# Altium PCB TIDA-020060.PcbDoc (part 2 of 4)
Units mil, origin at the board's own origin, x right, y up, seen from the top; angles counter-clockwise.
Board outline 2114.94 x 3612.21 mil, 4 copper layers (Top Layer, Signal Layer 1, Signal Layer 2, Bottom Layer), stack 61.811 mil thick; 272 components, 167 nets, 840 pads, 352 vias.
Unrouted connection lines stored in the file: 261.
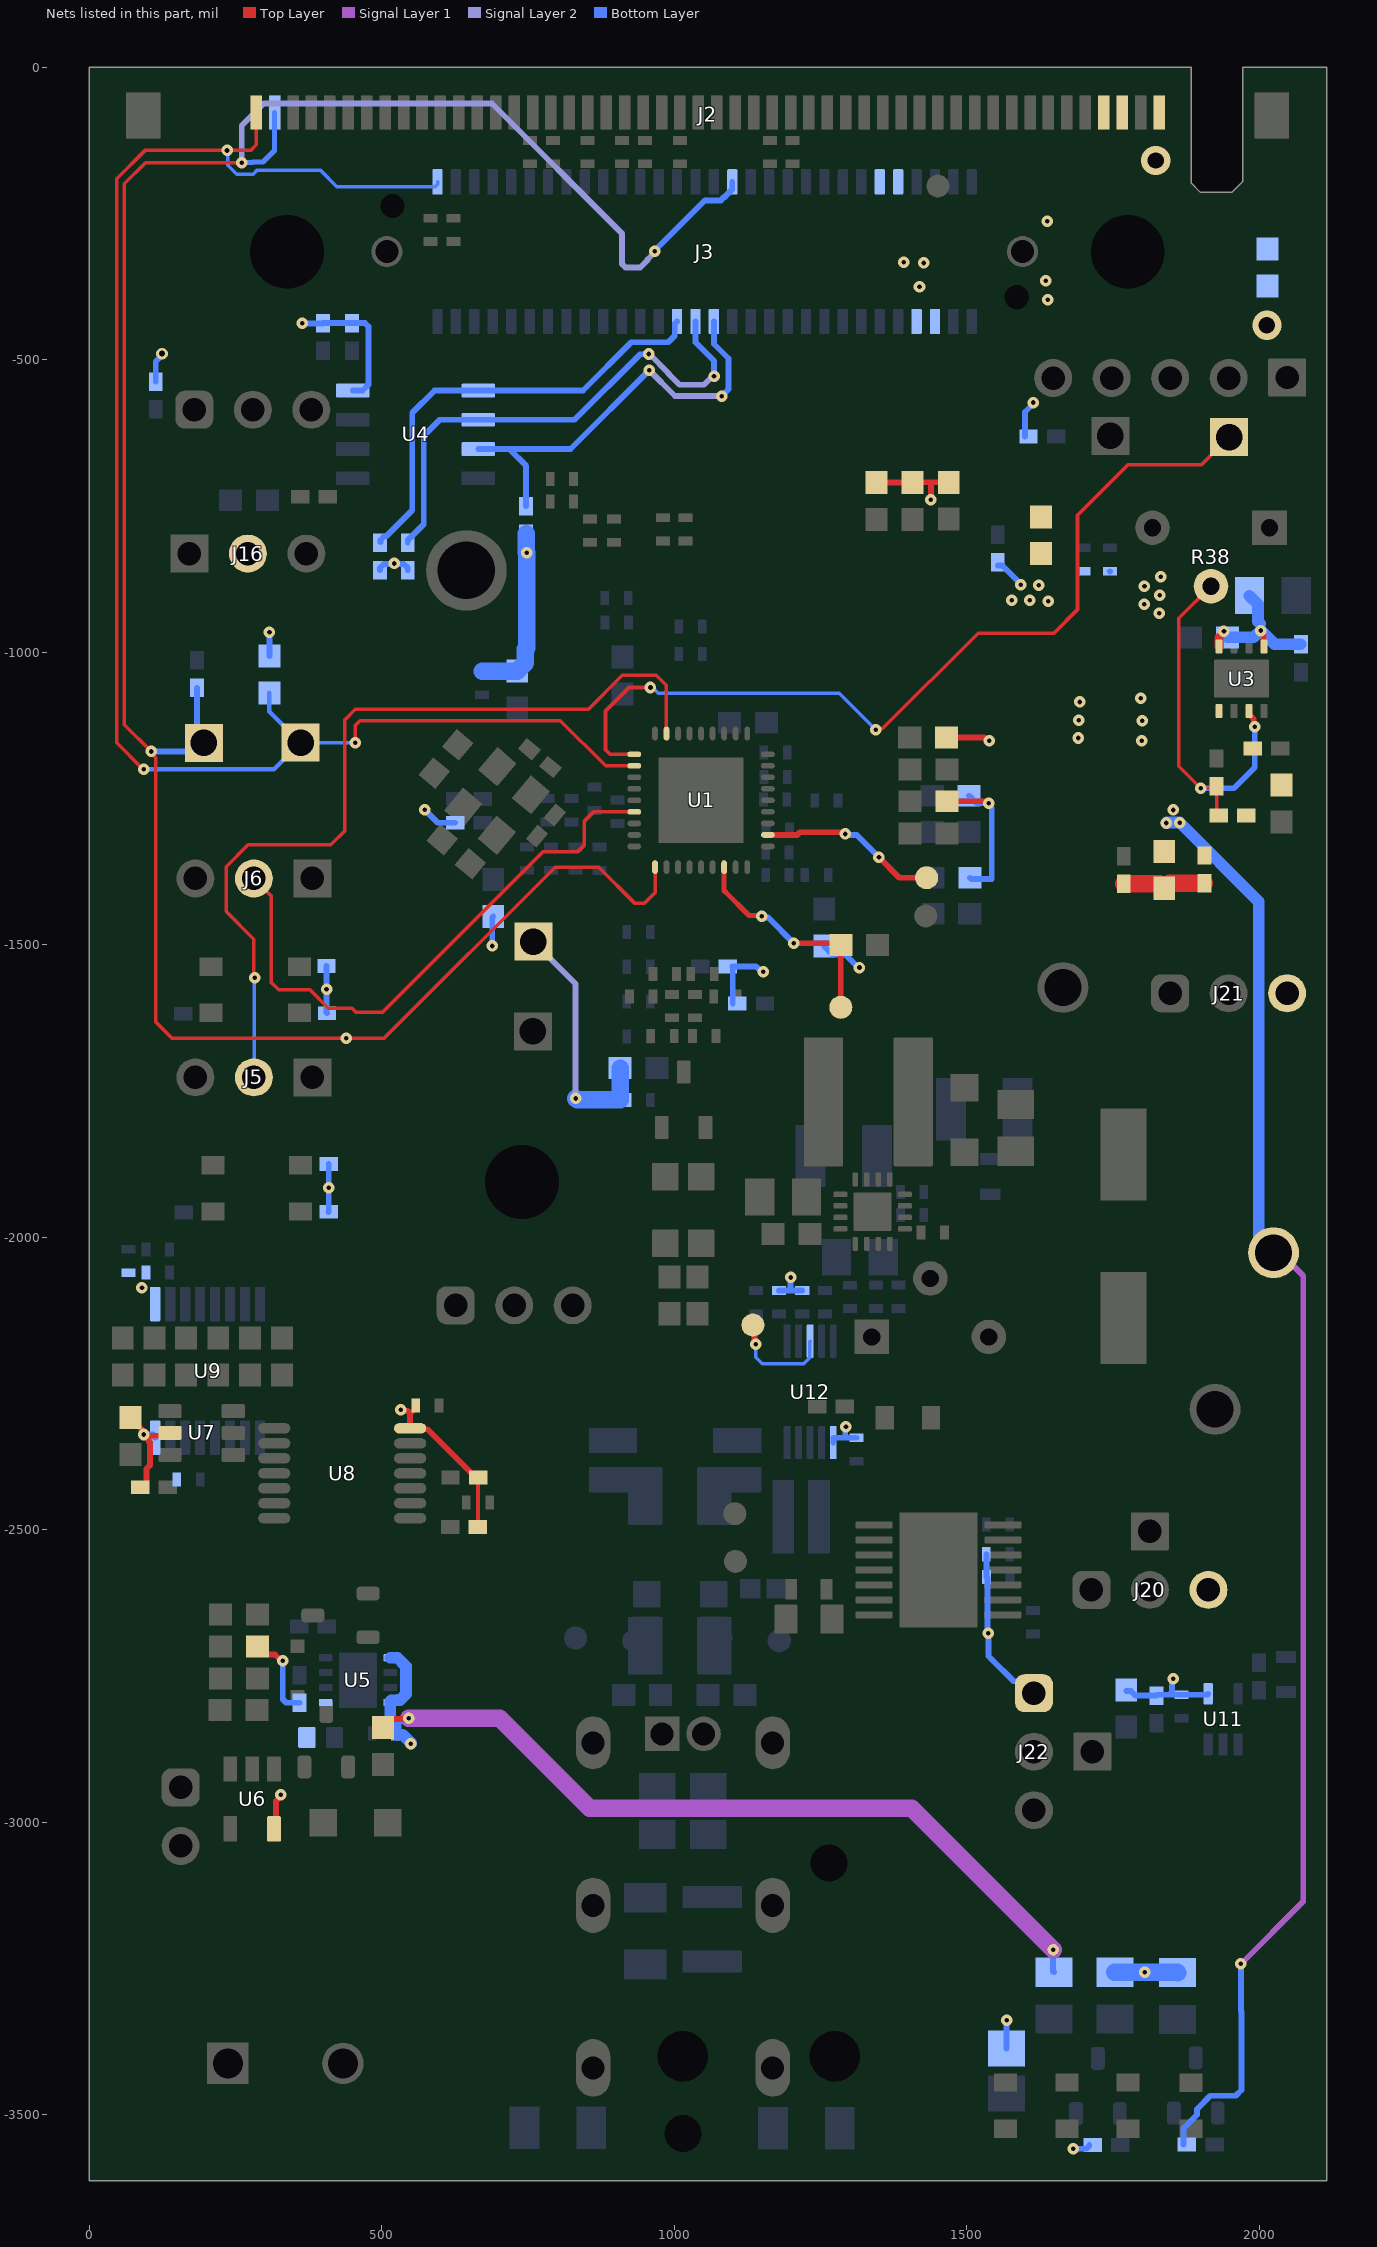
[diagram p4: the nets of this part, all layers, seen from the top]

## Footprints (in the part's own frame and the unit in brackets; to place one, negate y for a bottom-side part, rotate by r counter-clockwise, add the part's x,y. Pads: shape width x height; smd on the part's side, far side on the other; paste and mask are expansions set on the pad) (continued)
Samtec_ERF8-050-01-x-D-EM2 [mm] "Receptacle, 0.8mm, 50x2, Edge Mount"
  rect 0.5x1.48 smd paste-1: 1(-19.6,-2.06) 3(-18.8,-2.06) 5(-18,-2.06) 7(-17.2,-2.06) 9(-16.4,-2.06) 11(-15.6,-2.06) 13(-14.8,-2.06) 15(-14,-2.06) 17(-13.2,-2.06) 19(-12.4,-2.06) 21(-11.6,-2.06) 23(-10.8,-2.06) 25(-10,-2.06) 27(-9.2,-2.06) 29(-8.4,-2.06) 31(-7.6,-2.06) 33(-6.8,-2.06) 35(-6,-2.06) 37(-5.2,-2.06) 39(-4.4,-2.06) 41(-3.6,-2.06) 43(-2.8,-2.06) 45(-2,-2.06) 47(-1.2,-2.06) 49(-0.4,-2.06) 51(0.4,-2.06) 53(1.2,-2.06) 55(2,-2.06) 57(2.8,-2.06) 59(3.6,-2.06) 61(4.4,-2.06) 63(5.2,-2.06) 65(6,-2.06) 67(6.8,-2.06) 69(7.6,-2.06) 71(8.4,-2.06) 73(9.2,-2.06) 75(10,-2.06) 77(10.8,-2.06) 79(11.6,-2.06) 81(12.4,-2.06) 83(13.2,-2.06) 85(14,-2.06) 87(14.8,-2.06) 89(15.6,-2.06) 91(16.4,-2.06) 93(17.2,-2.06) 95(18,-2.06) 97(18.8,-2.06) 99(19.6,-2.06)
  rect 0.5x1.48 smd far side paste-1: 2(-19.6,-2.06) 4(-18.8,-2.06) 6(-18,-2.06) 8(-17.2,-2.06) 10(-16.4,-2.06) 12(-15.6,-2.06) 14(-14.8,-2.06) 16(-14,-2.06) 18(-13.2,-2.06) 20(-12.4,-2.06) 22(-11.6,-2.06) 24(-10.8,-2.06) 26(-10,-2.06) 28(-9.2,-2.06) 30(-8.4,-2.06) 32(-7.6,-2.06) 34(-6.8,-2.06) 36(-6,-2.06) 38(-5.2,-2.06) 40(-4.4,-2.06) 42(-3.6,-2.06) 44(-2.8,-2.06) 46(-2,-2.06) 48(-1.2,-2.06) 50(-0.4,-2.06) 52(0.4,-2.06) 54(1.2,-2.06) 56(2,-2.06) 58(2.8,-2.06) 60(3.6,-2.06) 62(4.4,-2.06) 64(5.2,-2.06) 66(6,-2.06) 68(6.8,-2.06) 70(7.6,-2.06) 72(8.4,-2.06) 74(9.2,-2.06) 76(10,-2.06) 78(10.8,-2.06) 80(11.6,-2.06) 82(12.4,-2.06) 84(13.2,-2.06) 86(14,-2.06) 88(14.8,-2.06) 90(15.6,-2.06) 92(16.4,-2.06) 94(17.2,-2.06) 96(18,-2.06) 98(18.8,-2.06) 100(19.6,-2.06)
  rect 1.5x2 smd: MP1(-24.5,-2.2) MP3(24.5,-2.2)
  rect 1.5x2 smd far side: MP2(-24.5,-2.2) MP4(24.5,-2.2)
  silkscreen extent -26.5,-5.2 26,-0.17, body extent -26,-5.2 26,7, height 2.14
SM_RADIAL_F [mm] "8 x 10.2mm:  Panasonic F"
  rect 4x2 smd: 1(-3.55,0) 2(3.55,0)
  silkscreen extent -4.25,-4.25 4.25,4.25, body extent -4.25,-4.25 4.25,4.25, height 10.5
SOD-123W [mm] "NXP recommended land pattern"
  rect 1.2x1.2 smd paste-0.05: 1(-1.4,0) 2(1.4,0)
  silkscreen extent -2.64,-1.14 1.68,1.14, body extent -1.85,-0.95 1.85,0.95, height 1.1
SOD-323 [mm] "NXP recommended land pattern"
  rect 0.6x0.6 smd paste-0.05: 1(-1.1,0) 2(1.1,0)
  silkscreen extent -2.06,-0.86 1.53,0.86, body extent -1.3,-0.67 1.3,0.68, height 1.1
SOIC-8 [mm] "duplicate of SO-8.  SOIC, 8-Leads, Body 5.0x4.0mm (max), Pitch 1.27mm, IPC Medium Density"
  rrect17% 1.45x0.6 smd: 1(-2.725,1.905) 2(-2.725,0.635) 3(-2.725,-0.635) 4(-2.725,-1.905) 5(2.725,-1.905) 6(2.725,-0.635) 7(2.725,0.635) 8(2.725,1.905)
  silkscreen extent -3.5,-2.5 0.9,2.5, body extent -3,-2.45 3,2.45, height 1.63
SOT-23 [mm] "SOT23, 3-Leads, Body 2.9x1.3mm, Pitch 0.95mm, Lead Span 2.5mm, IPC Medium Density"
  rrect50% 1x0.6 smd: 1(-1.2,0.95) 2(-1.2,-0.95) 3(1.2,0)
  silkscreen extent -1.62,-1.5 0.7,1.5, body extent -1.16,-1.45 1.21,1.45, height 1
SPC02SYAN [mil] "SULLINS"
  round 1 on Mech3: 0(0,0)
  body extent -98,-47 99,47, height 366
TE_1PORT_B1-B [mm] "Header, 1.8mm, 2x1, TH"
  rect 1.5x1.5 hole 1: 1(-0.9,17.35)
  round 1.5 hole 1: 2(0.9,17.35)
  round 0 hole 2.2 unplated: MH1(0,3.35) MH2(6.6,3.35)
  round 0 hole 1.6 unplated: MH3(6.35,11.75) MH4(0,0)
  oval 1.5x2.3 hole 1 slot 1.775 at 90 deg: S1(-3.9,16.963) S4(3.9,16.963)
  oval 1.5x2.4 hole 1 slot 1.89 at 90 deg: S2(-3.9,9.905) S5(3.9,9.905)
  oval 1.5x2.5 hole 1 slot 2 at 90 deg: S3(-3.9,2.85) S6(3.9,2.85)
  silkscreen extent -7.45,-1.8 10.3,20, body extent -7.45,-1.8 10.3,19.3, height 13.5
TI_Stacked_Overlay_Small [mil]
  silkscreen extent -418,-98 418,98
TP_SM_1MM [mm] "1mm Test Point, SMT"
  round 1 smd paste-0.5: 1(0,0)
TRIM_3266W [mm] "Bourns 3266W series REV 08/10"
  rect 1.5x1.5 hole 0.75: 1(0,0)
  round 1.5 hole 0.75: 2(2.54,-2.54) 3(0,-5.08)
  silkscreen extent -1.2,-6.09 3.68,1.01, body extent -1.2,-6.09 3.68,1.01, height 8.45
TSW-101-07-G-S [mm] "Samtec 100mil, 1pos, 230 mil above insulator"
  rrect6% 1.65x1.65 hole 1.016: 1(0,0)
  silkscreen extent -1.27,-1.27 1.27,1.27, body extent -1.27,-1.27 1.27,1.27, height 8.38
TSW-102-07-G-S [mm] "Samtec 100mil, 1x2, 230 mil above insulator"
  rrect50% 1.65x1.65 hole 1.016: 1(-1.27,0)
  round 1.65 hole 1.016: 2(1.27,0)
  silkscreen extent -3.3,-1.27 2.54,1.44, body extent -2.54,-1.27 2.54,1.27, height 8.38
TSW-103-07-G-S [mm] "Samtec 100mil, 1x3, 230 mil above insulator"
  rrect50% 1.65x1.65 hole 1.016: 1(-2.54,0)
  round 1.65 hole 1.016: 2(0,0) 3(2.54,0)
  body extent -3.81,-1.27 3.81,1.27, height 8.38
TSW-103-07-X-S [mm] "Samtec Header, 100mil, 1x3"
  rect 1.65x1.65 hole 1.016: 1(-2.54,0)
  round 1.65 hole 1.016: 2(0,0) 3(2.54,0)
  silkscreen extent -4.57,-1.52 4.06,1.52, body extent -3.81,-1.27 3.81,1.27, height 8.38
TSW-105-07-X-S [mm] "Samtec 100mil, 1x5, 230 mil above insulator"
  rrect6% 1.65x1.65 hole 1.016: 1(-5.08,-0.025)
  round 1.65 hole 1.016: 2(-2.54,0) 3(0,0) 4(2.54,0) 5(5.08,0)
  silkscreen extent -6.38,-1.25 6.37,1.25, body extent -6.35,-1.27 6.35,1.27, height 8.38
WEEE_Minimum [mil] "WEEElie bin"
  silkscreen extent -95,-172 99,104
WURTH_61300111121 [mm] "Header, 2.54 mm, 1x1, TH"
  rect 1.65x1.65 hole 1.15: 1(0,0)
  silkscreen extent -1.27,-1.27 1.27,1.27, body extent -1.27,-1.27 1.27,1.27, height 8.54

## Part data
C1 C33 C34 C36 C64: library part CMP-0006279-2, "CAP, CERM, 0.1 uF, 50 V, +/- 10%, X5R, 0402", Cap_Case=0402, Manufacturer=TDK, Supplier Part Number 1=445-5942-1-ND, TempCo=X5R, Tolerance_%=10%, Value1="0.039064 ohm", Value2=50V, ValueDisplayed=0.1uF
C2 C8 C11 C15 C22 C23 C35 C41: library part CMP-0006564-3, "CAP, CERM, 10 uF, 10 V, +/- 20%, X5R, 0402", Cap_Case=0402, Manufacturer=MuRata, TempCo=X5R, Tolerance_%=20%, Value1=Unknown, Value2=10V, ValueDisplayed=10uF
C3 C6 C12 C16 C24 C38 C44: library part CMP-0085818-1, "CAP, CERM, 1 µF, 10 V,+/- 10%, X7S, AEC-Q200 Grade 1, 0402", Cap_Case=0402, Manufacturer=MuRata, TempCo=X7S, Tolerance_%=10%, Value2=10V, ValueDisplayed=1µF
C4: library part CMP-0006669-2, "CAP, CERM, 0.047 uF, 25 V, +/- 10%, X7R, 0402", Cap_Case=0402, Manufacturer=MuRata, Supplier Part Number 1=490-3254-1-ND, TempCo=X7R, Tolerance_%=10%, Value1=Unknown, Value2=25V, ValueDisplayed=0.047uF
C5 C55: library part CMP-0006279-2, "CAP, CERM, 0.1 uF, 50 V, +/- 10%, X5R, 0402", Cap_Case=0402, Manufacturer=TDK, Supplier Part Number 1=445-5942-1-ND, TempCo=X5R, Tolerance_%=10%, Value1="0.039064 ohm", Value2=50V, ValueDisplayed=100nF
C7: library part CMP-0006467-2, "CAP, CERM, 47 pF, 50 V, +/- 1%, C0G/NP0, 0402", Cap_Case=0402, Manufacturer=MuRata, Supplier Part Number 1=490-6241-1-ND, TempCo=C0G/NP0, Tolerance_%=1%, Value1=Unknown, Value2=50V, ValueDisplayed=47pF
C9: library part CMP-0006438-2, "CAP, CERM, 22 pF, 50 V, +/- 1%, C0G/NP0, 0402", Cap_Case=0402, Manufacturer=MuRata, Supplier Part Number 1=490-8589-1-ND, TempCo=C0G/NP0, Tolerance_%=1%, Value1=Unknown, Value2=50V, ValueDisplayed=22pF
C10 C20: library part CMP-0007099-4, "CAP, CERM, 0.1 uF, 100 V, +/- 10%, X7S, AEC-Q200 Grade 1, 0603", Cap_Case=0603, Manufacturer=TDK, Supplier Part Number 1=445-6938-1-ND, TempCo=X7S, Tolerance_%=10%, Value1="0.04959 ohm", Value2=100V, ValueDisplayed=0.1uF
C13 C17 C25 C37 C39 C45 C51 C63 C65: library part CMP-0006237-2, "CAP, CERM, 0.1 uF, 16 V, +/- 10%, X7R, AEC-Q200 Grade 1, 0402", Cap_Case=0402, Manufacturer=Kemet, Supplier Part Number 1=399-6828-1-ND, TempCo=X7R, Tolerance_%=10%, Value1=Unknown, Value2=16V, ValueDisplayed=0.1uF
C14 C18 C26 C40 C43 C46: library part CMP-0006658-2, "CAP, CERM, 0.01 uF, 25 V, +/- 10%, X7R, 0402", Cap_Case=0402, Manufacturer=MuRata, Supplier Part Number 1=490-1312-1-ND, TempCo=X7R, Tolerance_%=10%, Value1=Unknown, Value2=25V, ValueDisplayed=0.01uF
C19: library part CMP-0008916-2, "CAP, CERM, 1000 pF, 1000 V, +/- 10%, X7R, 1206", Cap_Case=1206, Manufacturer=MuRata, Supplier Part Number 1=490-3494-1-ND, TempCo=X7R, Tolerance_%=10%, Value1=Unknown, Value2=1000V, ValueDisplayed=1000pF
C21: library part CMP-0006438-1, "CAP, CERM, 22 pF, 50 V, +/- 1%, C0G/NP0, 0402", Cap_Case=0402, Manufacturer=MuRata, Supplier Part Number 1=490-8589-1-ND, TempCo=C0G/NP0, Tolerance_%=1%, Value1=Unknown, Value2=50V, ValueDisplayed=22pF
C27: library part CMP-0006467-1, "CAP, CERM, 47 pF, 50 V, +/- 1%, C0G/NP0, 0402", Cap_Case=0402, Manufacturer=MuRata, Supplier Part Number 1=490-6241-1-ND, TempCo=C0G/NP0, Tolerance_%=1%, Value1=Unknown, Value2=50V, ValueDisplayed=47pF
C28 C29: library part CMP-0007071-4, "CAP, CERM, 22 pF, 50 V, +/- 5%, C0G/NP0, AEC-Q200 Grade 1, 0603", Cap_Case=0603, Manufacturer=TDK, Supplier Part Number 1=445-5632-1-ND, TempCo=C0G/NP0, Tolerance_%=5%, Value1=Unknown, Value2=50V, ValueDisplayed=22pF
C30: library part CMP-0120005-1, "Multilayer Ceramic Capacitor, 4700 pF, 2000 V, ± 10%, X7R, 1210 [3225 Metric]", Digikey Part Number=399-C1210C472KGRAC7800CT-ND, Manufacturer=KEMET, Mouser Part Number=80-C1210C472KGR, Operating Temperature Range="-55°C to +125°C", TempCo=15%, Temperature Characteristic=X7R, Tolerance_%=10%, ValueDisplayed=4700pF
C31: library part CMP-0008262-2, "CAP, CERM, 10 uF, 25 V, +/- 10%, X7S, 0805", Cap_Case=0805, Manufacturer=MuRata, Supplier Part Number 1=490-10496-1-ND, TempCo=X7S, Tolerance_%=10%, Value1=Unknown, Value2=25V, ValueDisplayed=10uF
C32: library part CMP-0007058-4, "CAP, CERM, 4.7 uF, 10 V, +/- 10%, X7S, 0603", Cap_Case=0603, Manufacturer=TDK, Supplier Part Number 1=445-14258-1-ND, TempCo=X7S, Tolerance_%=10%, Value1=Unknown, Value2=10V, ValueDisplayed=4.7uF
C42: library part CMP-0084773-1, "CAP, CERM, 0.01 µF, 100 V,+/- 10%, X7R, AEC-Q200 Grade 1, 0603", Cap_Case=0603, Manufacturer=MuRata, TempCo=X7R, Tolerance_%=10%, Value2=100V, ValueDisplayed=0.01µF
C47: library part CMP-0084301-1, "CAP, CERM, 10 µF, 6.3 V,+/- 20%, X7R, 0603", Cap_Case=0603, Manufacturer="Samsung Electro-Mechanics", TempCo=X7R, Tolerance_%=20%, Value2=6.3V, ValueDisplayed=10µF
C48: library part CMP-0120003-1, "2.2 µF ±20% 10V Ceramic Capacitor X5R 0603 (1608 Metric)", Digikey Part Number=399-C0603C225M8PAC7867CT-ND, Manufacturer=KEMET, Mouser Part Number=80-C0603C225M8P, Operating Temperature Range="-55°C to +85°C", TempCo=15%, Temperature Characteristic=X5R, Tolerance_%=20%, ValueDisplayed=2.2uF
C49: library part CMP-0084375-1, "CAP, CERM, 1 µF, 16 V,+/- 20%, X5R, 0402", Cap_Case=0402, Manufacturer=MuRata, TempCo=X5R, Tolerance_%=20%, Value2=16V, ValueDisplayed=1µF
C50: library part CMP-0006828-4, "CAP, CERM, 0.01 uF, 16 V, +/- 10%, X7R, 0603", Cap_Case=0603, Manufacturer="Wurth Elektronik", Supplier Part Number 1=732-7959-1-ND, TempCo=X7R, Tolerance_%=10%, Value1=Unknown, Value2=16V, ValueDisplayed=0.01uF
C52: library part CMP-0007080-5, "CAP, CERM, 0.068 uF, 50 V, +/- 10%, X7R, AEC-Q200 Grade 1, 0603", Cap_Case=0603, Manufacturer=TDK, Supplier Part Number 1=445-5665-1-ND, TempCo=X7R, Tolerance_%=10%, Value1="0.035979 ohm", Value2=50V, ValueDisplayed=0.068uF
C53: library part CMP-0007411-4, "CAP, CERM, 0.15 uF, 25 V, +/- 10%, X7R, 0603", Cap_Case=0603, Manufacturer=MuRata, Supplier Part Number 1=490-3289-1-ND, TempCo=X7R, Tolerance_%=10%, Value1=Unknown, Value2=25V, ValueDisplayed=0.15uF
C54: library part CMP-0006832-5, "CAP, CERM, 0.1 uF, 25 V, +/- 10%, X7R, 0603", Cap_Case=0603, Manufacturer="Wurth Elektronik", Supplier Part Number 1=710-885012206071, TempCo=X7R, Tolerance_%=10%, Value1=Unknown, Value2=25V, ValueDisplayed=0.1uF
C56: library part CMP-0007886-2, "CAP, CERM, 0.1 uF, 100 V, +/- 10%, X7R, 0805", Cap_Case=0805, Manufacturer=TDK, Supplier Part Number 1=445-1418-1-ND, TempCo=X7R, Tolerance_%=10%, Value1="0.020726 ohm", Value2=100V, ValueDisplayed=0.1uF
C57 C70: library part CMP-0009182-2, "CAP, CERM, 4.7 uF, 100 V, +/- 10%, X7S, 1210", Cap_Case=1210, Manufacturer=MuRata, Supplier Part Number 1=81-GRM32DC72A475KE1L, TempCo=X7S, Tolerance_%=10%, Value1=Unknown, Value2=100V, ValueDisplayed=4.7uF
C58 C68: library part CMP-0007469-4, "CAP, CERM, 0.1 uF, 100 V, +/- 10%, X7R, 0603", Cap_Case=0603, Manufacturer=MuRata, Supplier Part Number 1=490-3285-1-ND, TempCo=X7R, Tolerance_%=10%, Value1=Unknown, Value2=100V, ValueDisplayed=0.1uF
C59: library part CMP-0007980-2, "CAP, CERM, 1 uF, 100 V, +/- 10%, X7S, AEC-Q200 Grade 1, 0805", Cap_Case=0805, Manufacturer=TDK, Supplier Part Number 1=445-6974-1-ND, TempCo=X7S, Tolerance_%=10%, Value1="0.008255 ohm", Value2=100V, ValueDisplayed=1uF
C60: library part CMP-0006655-2, "CAP, CERM, 0.068 uF, 16 V, +/- 10%, X7R, 0402", Cap_Case=0402, Manufacturer=MuRata, Supplier Part Number 1=490-3259-1-ND, TempCo=X7R, Tolerance_%=10%, Value1=Unknown, Value2=16V, ValueDisplayed=0.068uF
C61: library part CMP-0007704-2, "CAP, CERM, 10 pF, 50 V, +/- 5%, C0G/NP0, 0805", Cap_Case=0805, Manufacturer=Kemet, Supplier Part Number 1=399-1108-1-ND, TempCo=C0G/NP0, Tolerance_%=5%, Value1="0.285 ohm", Value2=50V, ValueDisplayed=10pF
C62: library part CMP-0860997-1, "CAP, CERM, 1000 pF, 50 V,+/- 10%, X8R, AEC-Q200 Grade 0, 0402", Cap_Case=0402, Manufacturer=TDK, TempCo=X8R, Tolerance_%=10%, Value2=50V, ValueDisplayed=1000pF
C67: library part CMP-0008249-2, "CAP, CERM, 0.22 uF, 100 V, +/- 10%, X7R, 0805", Cap_Case=0805, Manufacturer=MuRata, Supplier Part Number 1=GRM21AR72A224KAC5-ND, TempCo=X7R, Tolerance_%=10%, Value1=Unknown, Value2=100V, ValueDisplayed=0.22uF
C69: library part CMP-0011202-2, "CAP, AL, 22 uF, 100 V, +/- 20%, 1.3 ohm, AEC-Q200 Grade 2, SMD", Cap_Case=F, Manufacturer=Panasonic, Supplier Part Number 1=PCE3845CT-ND, Tolerance_%=20%, Value1="1.3 ohm", Value2=100V, ValueDisplayed=22uF
D1 D5 D6 D7 D8 D9 D10 D13 D15: library part CMP-0002971-3, "LED, Green, SMD", Color=Green, Manufacturer=OSRAM, Value1=W, Value2=1.8V
D2 D3: library part CMP-0086344-2, "Diode, TVS, Bi, AEC-Q101, 0603", Manufacturer=Panasonic
D4: library part CMP-0085742-1, "Diode, Zener, 5.6 V, 300 mW, AEC-Q101, SOD-323", Manufacturer="ON Semiconductor", Power_W=300mW, Value1=0.3W
D11 D12: library part CMP-0076989-2, "Diode, Schottky, 60 V, 2 A, SOD-123W", Manufacturer=Nexperia, Value1=2A, Value2=0.53V
FB1: library part CMP-06046-000009-2, "Chip Ferrite Bead, 0603, 1000Ω @ 100MHz, 0.2Ω, 25%, 1A", Case Code (Imperial)=0603, Case Code (Metric)=1608, DC Resistance (DCR)=200mR, Max Current Rating=1A, Max Operating Temperature=125°C, Min Operating Temperature=-55°C, Ratings=AEC-Q200
H1 H2 H13: library part CMP-0003617-1, "Machine Screw, Round, #4-40 x 1/4, Nylon, Philips panhead", Manufacturer="B&F Fastener Supply", Supplier Part Number 1=H542-ND
J1: library part CMP-0054903-2, "Header(shrouded), 2x1, R/A, TH", Manufacturer="TE Connectivity"
J2: library part CMP-0055719-1, "Receptacle, 0.8mm, 50x2, Gold, Edge Mount", Color=Black, Current_A=2.2A, Manufacturer=Samtec, Voltage_V=200V
J3: library part CMP-0086037-1, "Receptacle, 0.8mm, 30x2, Gold, SMT", Color=Black, Current_A=800mA, Manufacturer=Molex, Voltage_V=5V
J4 J8 J9 J12 J13 J19: library part CMP-0054792-1, "Header, 2.54 mm, 1x1, Gold, TH", Manufacturer="Wurth Elektronik", Supplier Part Number 1=732-5314-ND
J5 J6 J16: library part CMP-0075407-1, "Header, 100mil, 3x1, Gold, TH", Color=Black, Current_A=6.3A, Manufacturer=Samtec, Supplier Part Number 1=SAM1029-03-ND, Voltage_V=550V
J7: library part CMP-0075411-1, "Header, 100mil, 5x1, Gold, TH", Color=Black, Current_A=6.3A, Manufacturer=Samtec, Supplier Part Number 1=SAM1029-05-ND, Voltage_V=550V
J11 J17 J20 J21 J22: library part CMP-0075407-2, "Header, 100mil, 3x1, Gold, TH", Color=Black, Current_A=6.3A, Manufacturer=Samtec, Supplier Part Number 1=SAM1029-03-ND, Voltage_V=550V
J14: library part CMP-0055502-1, "Therminal Block, 5 mm, 2-pole, TH", Manufacturer="Phoenix Contact", Supplier Part Number 1=277-1667-ND
J15: library part CMP-0075405-3, "Header, 100mil, 2x1, Gold, TH", Color=Black, Current_A=6.3A, Manufacturer=Samtec, Supplier Part Number 1=SAM1029-02-ND, Voltage_V=550V
J18 J23: library part CMP-0075403-1, "Header, 100mil, 1pos, Gold, TH", Color=Black, Current_A=6.3A, Manufacturer=Samtec, Supplier Part Number 1=SAM1029-01-ND, Voltage_V=550V
L1: library part CMP-0003343-2, "Ferrite Bead, 1000 ohm @ 100 MHz, 0.4 A, 0603", Manufacturer=MuRata, Supplier Part Number 1=490-1015-1-ND, Value1="0.5 ohm", Value2=0.4A, ValueDisplayed="1000 ohm"
L2: library part CMP-0098175-1, "Differential Mode Choke 3.9uH 540mA 0.36Ohm 3.2x2.5x2.5mm SMT", Manufacturer=TDK, Operating Temperature Range="-40°C to +150°C", Test Frequency=100kHz, Tolerance_%=20%
L3 L4: library part CMP-0003343-1, "Ferrite Bead, 1000 ohm @ 100 MHz, 0.4 A, 0603", Manufacturer=MuRata, Supplier Part Number 1=490-1015-1-ND, Value1="0.5 ohm", Value2=0.4A, ValueDisplayed="1000 ohm"
L5: library part CMP-0098176-1, "Differential Mode Choke 2.6uH 1.5A 84mOhm 7.0x6.0x3.5mm SMT", Manufacturer=TDK, Operating Temperature Range="-40°C to +150°C", Self Resonant Frequency=20MHz, Test Frequency=100kHz, Tolerance_%=20%
L6 L7: library part CMP-0121122-1, "Wire Wound Ferrite Inductor for Automotive 3.3μH ±5% 0.24Ω 425mA 1210", Manufacturer=Murata, Operating Temperature Range="-40°C to +125°C", Self Resonant Frequency=65MHz, Test Frequency=1MHz, Tolerance_%=0.05%
L8: library part CMP-0098174-1, "Common Mode Choke for Ethernet 1000BASE-T1", Manufacturer=TDK, Operating Temperature Range="to +125°C", Test Frequency=100kHz, Tolerance_%=30%
L9: library part CMP-0098310-1, "10 µH Shielded Inductor 3.3 A 70.2mOhm Max Nonstandard", Digikey Part Number=732-78438367100CT-ND, Manufacturer="Wurth Electronics", Mouser Part Number=710-78438367100, Operating Temperature Range="-40°C to +125°C", Self Resonant Frequency=13MHz, Test Frequency=100kHz, Tolerance_%=20%
L12: library part CMP-0001515-1, "Differential Mode Choke 18uH 1.8A 0.103 Ohm 7.5x7.5x7.5mm SMT", Manufacturer=TDK, Operating Temperature Range="-40°C to +150°C", Test Frequency=100kHz, Tolerance_%=20%
LBL4: library part CMP-0003625-1, "Thermal Transfer Printable Labels, 0.650\" W x 0.200\" H - 10,000 per roll", Manufacturer=Brady, Supplier Part Number 1=97C5133
Logo8: library part CMP-0074769-3, Manufacturer="Texas Instruments"
Logo9: library part CMP-0074844-1
Logo10: library part CMP-0074838-1, "Texas Instrument Corporate Signature"
Logo11: library part CMP-0074847-1, "FCC_disclaimer"
Q1 Q3: library part CMP-0000376-2, "Transistor, NPN, 45 V, 0.1 A, SOT-23", Manufacturer="ON Semiconductor", Supplier Part Number 1=BC847CLT1GOSCT-ND, Value1="0.1 A", Value2=800
Q2: library part CMP-0000325-2, "Transistor, PNP, 40 V, 0.2 A, SOT-23", Manufacturer="Fairchild Semiconductor", Supplier Part Number 1=MMBT3906FSCT-ND, Value1="0.2 A", Value2=300
Q5: library part CMP-0000971-2, "MOSFET, N-CH, 100 V, 1.4 A, SOT-23", Alternate Manufacturer=None, Manufacturer="Diodes Inc.", Supplier Part Number 1=DMN10H220L-7DICT-ND, Value1=0.2, Value2="4.1 nC"
R1 R33: library part CMP-0021108-3, "RES, 2.10 k, 1%, 0.125 W, AEC-Q200 Grade 0, 0805", Manufacturer=Vishay-Dale, Power_W=125mW, Supplier Part Number 1=541-2.10KCCT-ND, TempCo="100 ppm/C", Tolerance_%=1%, Value2=0.125W, Value_Code=2k10, ValueDisplayed=2.10k
R2 R3 R4 R5 R6 R14 R24 R32 R35 R59 R67: library part CMP-0022277-4, "RES, 2.49 k, 1%, 0.1 W, AEC-Q200 Grade 0, 0603", Manufacturer=Vishay-Dale, Power_W=100mW, Supplier Part Number 1=541-2.49KHCT-ND, TempCo="100 ppm/C", Tolerance_%=1%, Value2=0.1W, Value_Code=2k49, ValueDisplayed=2.49k
R7 R10: library part CMP-0026888-2, "RES, 27, 5%, 0.063 W, 0402", Manufacturer=Vishay-Dale, Power_W=63mW, Supplier Part Number 1=541-27JCT-ND, TempCo="200 ppm/C", Tolerance_%=5%, Value2=0.063W, Value_Code=27R0, ValueDisplayed=27
R8 R9 R62 R69 R87 R99 R100: library part CMP-0081856-1, "RES, 0, 0%, 0.2 W, AEC-Q200 Grade 0, 0402", Manufacturer=Vishay-Dale, Power_W=200mW, Supplier Part Number 1=541-0.0YBTR-ND, Tolerance_%=0%, Value2=0.2W, Value_Code=0
R11 R12: library part CMP-0020951-1, "RES, 1.00 k, 1%, 0.125 W, 0805", Manufacturer=Vishay-Dale, Power_W=125mW, Supplier Part Number 1=541-1.00KCCT-ND, TempCo="100 ppm/C", Tolerance_%=1%, Value2=0.125W, Value_Code=1k00, ValueDisplayed=1.00k
R13: library part CMP-0017285-3, "RES, 100 k, 1%, 0.25 W, AEC-Q200 Grade 0, 1206", Manufacturer=Panasonic, Power_W=250mW, Supplier Part Number 1=P100KFCT-ND, TempCo="100 ppm/C", Tolerance_%=1%, Value2=0.25W, Value_Code=100k
R15 R22 R71 R72 R73 R74: library part CMP-0023343-3, "RES, 0, 1%, 0.1 W, AEC-Q200 Grade 0, 0603", Manufacturer="Stackpole Electronics Inc", Power_W=100mW, Supplier Part Number 1=RMCF0603ZT0R00CT-ND, TempCo=ppm/C, Tolerance_%=1%, Value2=0.1W, Value_Code=0
R16 R34 R39 R40 R45 R46 R75 R104 R105 R106 R107 R110 R116: library part CMP-0027007-2, "RES, 0, 5%, 0.063 W, AEC-Q200 Grade 0, 0402", Manufacturer="KOA Speer", Power_W=63mW, Supplier Part Number 1=660-RK73Z1ETTP, TempCo=ppm/C, Tolerance_%=5%, Value2=0.063W, Value_Code=0000, ValueDisplayed=0
R18: library part CMP-0018610-3, "RES, 1.0 M, 5%, 0.25 W, AEC-Q200 Grade 0, 1206", Manufacturer=Vishay-Dale, Power_W=250mW, Supplier Part Number 1=541-1.0MECT-ND, TempCo="200 ppm/C", Tolerance_%=5%, Value2=0.25W, Value_Code=1M00, ValueDisplayed=1.0M
R19 R68 R93: library part CMP-0026890-5, "RES, 2.2 k, 5%, 0.063 W, AEC-Q200 Grade 0, 0402", Manufacturer=Vishay-Dale, Power_W=63mW, Supplier Part Number 1=541-2.2KJCT-ND, TempCo="200 ppm/C", Tolerance_%=5%, Value2=0.063W, Value_Code=2k20, ValueDisplayed=2.2k
R20 R21 R41 R60 R70 R84 R85 R86 R90 R91 R92: library part CMP-0026754-1, "RES, 10.0 k, 1%, 0.063 W, AEC-Q200 Grade 0, 0402", Manufacturer="Stackpole Electronics Inc", Power_W=63mW, Supplier Part Number 1=RMCF0402FT10K0CT-ND, TempCo="100 ppm/C", Tolerance_%=1%, Value2=0.063W, Value_Code=10k0, ValueDisplayed=10.0k
R23 R63 R64 R65: library part CMP-0026890-5, "RES, 2.2 k, 5%, 0.063 W, AEC-Q200 Grade 0, 0402", Manufacturer=Vishay-Dale, Power_W=63mW, Supplier Part Number 1=541-2.2KJCT-ND, TempCo="200 ppm/C", Tolerance_%=5%, Value2=0.063W, Value_Code=2k20, ValueDisplayed=2k2
R25 R26: library part CMP-0026237-1, "RES, 2.49 k, 1%, 0.063 W, 0402", Manufacturer=Vishay-Dale, Power_W=63mW, Supplier Part Number 1=541-2.49KLCT-ND, TempCo="100 ppm/C", Tolerance_%=1%, Value2=0.063W, Value_Code=2k49, ValueDisplayed=2.49k
R27 R28 R43 R44: library part CMP-0026934-1, "RES, 470, 5%, 0.063 W, 0402", Manufacturer=Vishay-Dale, Power_W=63mW, Supplier Part Number 1=541-470JCT-ND, TempCo="200 ppm/C", Tolerance_%=5%, Value2=0.063W, Value_Code=470R, ValueDisplayed=470
R29 R31: library part CMP-0022454-4, "RES, 4.53 k, 1%, 0.1 W, AEC-Q200 Grade 0, 0603", Manufacturer=Vishay-Dale, Power_W=100mW, Supplier Part Number 1=541-4.53KHCT-ND, TempCo="100 ppm/C", Tolerance_%=1%, Value2=0.1W, Value_Code=4k53, ValueDisplayed=4.53k
R30: library part CMP-0025951-1, "RES, 100, 1%, 0.063 W, 0402", Manufacturer=Vishay-Dale, Power_W=63mW, Supplier Part Number 1=541-100LCT-ND, TempCo="100 ppm/C", Tolerance_%=1%, Value2=0.063W, Value_Code=100R, ValueDisplayed=100
R36 R37: library part CMP-0026409-2, "RES, 5.0k, 1%, 0.063 W, AEC-Q200 Grade 0, 0402", Manufacturer=Vishay-Dale, Power_W=63mW, Supplier Part Number 1=541-4.42KLCT-ND, TempCo="100 ppm/C", Tolerance_%=1%, Value2=0.063W, Value_Code=4k42, ValueDisplayed=5.0k
R38: library part CMP-0002067-2, "Trimmer, 5k ohm, 0.25W, TH", Manufacturer=Bourns, Supplier Part Number 1=3266W-502LF-ND
R42 R81 R88 R89: library part CMP-0024586-3, "RES, 10.0 k, 0.5%, 0.1 W, 0603", Manufacturer="Yageo America", Power_W=100mW, Supplier Part Number 1=603-RT0603DRE0710KL, TempCo="50 ppm/C", Tolerance_%=0.5%, Value2=0.1W, Value_Code=10k0, ValueDisplayed=10.0k
R47 R48 R49 R50 R51 R52 R53 R54 R55 R56 R57 R58: library part CMP-0026997-2, "RES, 22, 5%, 0.1 W, AEC-Q200 Grade 0, 0402", Manufacturer=Panasonic, Power_W=100mW, Supplier Part Number 1=P22JCT-ND, TempCo="200 ppm/C", Tolerance_%=5%, Value2=0.1W, Value_Code=22R0, ValueDisplayed=22
R61: library part CMP-0020572-3, "RES, 5.1 k, 5%, 0.125 W, AEC-Q200 Grade 0, 0805", Manufacturer=Vishay-Dale, Power_W=125mW, Supplier Part Number 1=541-5.1KACT-ND, TempCo="200 ppm/C", Tolerance_%=5%, Value2=0.125W, Value_Code=5k10, ValueDisplayed=5.1k
R66: library part CMP-0020951-3, "RES, 1.00 k, 1%, 0.125 W, AEC-Q200 Grade 0, 0805", Manufacturer=Vishay-Dale, Power_W=125mW, Supplier Part Number 1=541-1.00KCCT-ND, TempCo="100 ppm/C", Tolerance_%=1%, Value2=0.125W, Value_Code=1k00, ValueDisplayed=1.00k
R76: library part CMP-0023081-5, "RES, 3.30 k, 1%, 0.1 W, 0603", Manufacturer=Yageo, Power_W=100mW, Supplier Part Number 1=311-3.30KHRCT-ND, TempCo="100 ppm/C", Tolerance_%=1%, Value2=0.1W, Value_Code=3k30, ValueDisplayed=3.30k
R77: library part CMP-0023240-5, "RES, 68.1, 1%, 0.1 W, 0603", Manufacturer=Yageo, Power_W=100mW, Supplier Part Number 1=311-68.1HRCT-ND, TempCo="100 ppm/C", Tolerance_%=1%, Value2=0.1W, Value_Code=68R1, ValueDisplayed=68.1
R78: library part CMP-0025997-3, "RES, 130 k, 1%, 0.063 W, AEC-Q200 Grade 0, 0402", Manufacturer=Vishay-Dale, Power_W=63mW, Supplier Part Number 1=541-130KLCT-ND, TempCo="100 ppm/C", Tolerance_%=1%, Value2=0.063W, Value_Code=130k
R79: library part CMP-0022986-5, "RES, 2.20 k, 1%, 0.1 W, 0603", Manufacturer=Yageo, Power_W=100mW, Supplier Part Number 1=311-2.20KHRCT-ND, TempCo="100 ppm/C", Tolerance_%=1%, Value2=0.1W, Value_Code=2k20, ValueDisplayed=2.20k
R80 R109: library part CMP-0065358-1, "RES, 20.0 k, .1%, .0625 W, 0402", Manufacturer="Yageo America", Power_W=62.5mW, Supplier Part Number 1=YAG1388CT-ND, TempCo="25 ppm/C", Tolerance_%=0.1%, Value1=.1%, Value2=.0625W, Value_Code=20k0, ValueDisplayed=20.0k
R82: library part CMP-0024575-3, "RES, 107 k, 0.5%, 0.1 W, 0603", Manufacturer="Yageo America", Power_W=100mW, TempCo="50 ppm/C", Tolerance_%=0.5%, Value2=0.1W, Value_Code=107k
R83: library part CMP-0023620-3, "RES, 91.0 k, 0.1%, 0.1 W, 0603", Manufacturer="Susumu Co Ltd", Power_W=100mW, Supplier Part Number 1=RG16P91.0KBCT-ND, TempCo="25 ppm/C", Tolerance_%=0.1%, Value2=0.1W, Value_Code=91k0, ValueDisplayed=91.0k
R95: library part CMP-0086261-1, "RES, 100 k, 0.5%, 0.1 W, AEC-Q200 Grade 0, 0603", Manufacturer=Vishay-Dale, Power_W=100mW, TempCo="50 ppm/C", Tolerance_%=0.5%, Value2=0.1W, Value_Code=100k
R96: library part CMP-0002069-2, "Trimmer, 50k ohm, 0.25W, TH", Manufacturer=Bourns, Supplier Part Number 1=3266W-503LF-ND
R97 R98: library part CMP-0026938-5, "RES, 4.7 k, 5%, 0.063 W, AEC-Q200 Grade 0, 0402", Manufacturer=Vishay-Dale, Power_W=63mW, Supplier Part Number 1=541-4.7KJCT-ND, TempCo="200 ppm/C", Tolerance_%=5%, Value2=0.063W, Value_Code=4k70, ValueDisplayed=4.7k
R101: library part CMP-0026237-2, "RES, 2.49 k, 1%, 0.063 W, AEC-Q200 Grade 0, 0402", Manufacturer=Vishay-Dale, Power_W=63mW, Supplier Part Number 1=541-2.49KLCT-ND, TempCo="100 ppm/C", Tolerance_%=1%, Value2=0.063W, Value_Code=2k49, ValueDisplayed=2.49k
R102: library part CMP-0026622-3, "RES, 9.76 k, 1%, 0.063 W, AEC-Q200 Grade 0, 0402", Manufacturer=Vishay-Dale, Power_W=63mW, Supplier Part Number 1=541-9.76KLCT-ND, TempCo="100 ppm/C", Tolerance_%=1%, Value2=0.063W, Value_Code=9k76, ValueDisplayed=9.76k
R103: library part CMP-0026911-3, "RES, 36 k, 5%, 0.063 W, AEC-Q200 Grade 0, 0402", Manufacturer=Vishay-Dale, Power_W=63mW, Supplier Part Number 1=541-36KJCT-ND, TempCo="200 ppm/C", Tolerance_%=5%, Value2=0.063W, Value_Code=36k0, ValueDisplayed=36k
R108: library part CMP-0015056-3, "RES, 0.05, 1%, 1 W, AEC-Q200 Grade 0, 0612", Manufacturer=Panasonic, Power_W=1W, Supplier Part Number 1=P18935CT-ND, TempCo="150 ppm/C", Tolerance_%=1%, Value_Code=R050, ValueDisplayed=0.05
R111: library part CMP-0025765-4, "RES, 270, 5%, 0.1 W, AEC-Q200 Grade 0, 0603", Manufacturer=Vishay-Dale, Power_W=100mW, Supplier Part Number 1=541-270GCT-ND, TempCo="200 ppm/C", Tolerance_%=5%, Value2=0.1W, Value_Code=270R, ValueDisplayed=270
R112 R113 R114: library part CMP-0026740-1, "RES, 4.99 k, 1%, 0.063 W, 0402", Manufacturer="Yageo America", Power_W=63mW, Supplier Part Number 1=311-4.99KLRCT-ND, TempCo="100 ppm/C", Tolerance_%=1%, Value2=0.063W, Value_Code=4k99, ValueDisplayed=4.99k
R115: library part CMP-0026709-1, "RES, 71.5 k, 1%, 0.1 W, AEC-Q200 Grade 0, 0402", Manufacturer=Panasonic, Power_W=100mW, Supplier Part Number 1=P71.5KLCT-ND, TempCo="100 ppm/C", Tolerance_%=1%, Value2=0.1W, Value_Code=71k5, ValueDisplayed=71.5k
SH-J1 SH-J2 SH-J3 SH-J5: library part CMP-0003642-1, "Shunt, 100mil, Flash Gold, Black", Manufacturer="Sullins Connector Solutions", Supplier Part Number 1=S9001-ND
TP2 TP5 TP6 TP8 TP9 TP11 TP13: library part CMP-0003825-1, "1mm Test Point, SMT", Manufacturer=Any
TP3 TP10: library part CMP-0055156-2, "Test Point, Multipurpose, Blue, TH", Color=Blue, Manufacturer="Keystone Electronics", Supplier Part Number 1=36-5127-ND
TP4: library part CMP-0055156-1, "Test Point, Multipurpose, Blue, TH", Color=Blue, Manufacturer=Keystone, Supplier Part Number 1=36-5127-ND
TP24: library part CMP-0055113-1, "Terminal, Turret, TH, Double", Manufacturer=Keystone, Supplier Part Number 1=36-1502-2-ND
U1: library part CMP-0085268-1, "Low Power Auto PHY 1000BASE-T1 Automotive Ethernet Physical Layer Transceiver, RND0036A (VQFNP-36)", Alternate Manufacturer="Texas Instruments", Alternate PartNumber=DP83TG720SWRNDTQ1
U2: library part CMP-0073594-1, "Automotive Dual-Channel High-Speed ESD Protection Device, DBZ0003A (SOT-23-3)", Alternate Manufacturer="Texas Instruments"
U3: library part CMP-0860764-1, "500-mA LDO With Power-Good in Small Wettable Flank WSON Package, DRB0008J (VSON-8)", Alternate Manufacturer="Texas Instruments"
U4: library part CMP-0005313-2, "256 kb I2C CMOS Serial EEPROM, SOIC-8", Manufacturer="ON Semiconductor", Supplier Part Number 1=CAT24C256WI-GT3OSCT-ND
U5: library part CMP-0092470-1, "Automotive, adjustable- and fixed-output, 500-mA, 16-V, positive-voltage, LDO linear regulator 8-SON -40 to 150", Dropout Voltage=0.75V, Manufacturer="Texas Instruments", Max Supply Voltage=16V, Min Supply Voltage=2.5V, Mouser Part Number=595-TLV76601QWDRBRQ1, Nominal Supply Current=50uA, Operating Temperature Range="-40°C to +150°C", Output Voltage=0.8-14.6V
U6: library part CMP-0120008-1, "Automotive-grade, single, 40-V, 4.5-MHz, low-power operational amplifier 5-SOT-23 -40 to 125", Digikey Part Number=296-OPA991QDBVRQ1CT-ND, Input Bias Current=0.00001uA, Input Offset Voltage=0.125mV, Manufacturer="Texas Instruments", Max Dual Supply Voltage=20V, Max Supply Voltage=40V, Min Dual Supply Voltage=1.35V, Min Supply Voltage=2.7V, Mouser Part Number=595-OPA991QDBVRQ1, Nominal Supply Current=560uA, Operating Temperature Range="-40°C to +125°C", Output Current Per Channel=75mA, Voltage Gain=145dB
U7: library part CMP-0084585-1, "Micropower, 18V Window Comparator with 400mV Reference, DDC0006A (SOT-23-THIN-6)", Alternate Manufacturer="Texas Instruments", Alternate PartNumber=TLV6700DDCT, Operating Temperature Range="-40 to 125 C", Rating=Catalog
U8: library part CMP-0050540-1, "Automotive Catalog Quadruple 2-Input Positive-NOR Gates, PW0014A, LARGE T&R", F @ Nom Voltage(Max)(Mhz)=110, Generic Part Number=SN74AHC02-Q1, ICC @ Nom Voltage(Max)(mA)=0.02, Manufacturer="Texas Instruments", Operating Temperature Range(C)="-40 to 125", Rating=Automotive, tpd @ Nom Voltage(Max)(ns)=13,8.5, Voltage(Nom)(V)=3.3,5
U9: library part CMP-0091949-1, "IC I/O EXPANDER I2C 8B 16TSSOP", Digikey Part Number=296-44902-1-ND, Frequency_Fixed=400kHz, Manufacturer="Texas Instruments", Max Supply Voltage=3.6V, Min Supply Voltage=1.65V, Mouser Part Number=595-TCA6408AQPWRQ1, Nominal Supply Current=9mA, Operating Temperature Range="-40°C to +125°C"
U10: library part CMP-0091836-5, "2.2-MHz Wide VIN 85-V Boost/Sepic/Flyback Converter with Dual Random Spread Spectrum", Manufacturer="Texas Instruments", Max Supply Voltage=60V, Min Supply Voltage=1.5V, Nominal Supply Current=670uA, Operating Temperature Range="-40°C to +150°C", Output Voltage=83V, Switching Frequency=100-2200kHz
U11: library part CMP-0120009-1, "Low-Power Comparator with Precision Reference", Digikey Part Number=296-TLV4011QDCKRQ1CT-ND, Manufacturer="Texas Instruments", Max Supply Voltage=6V, Min Supply Voltage=1.3V, Mouser Part Number=595-TLV4011QDCKRQ1, Nominal Supply Current=2uA, Operating Temperature Range="-40°C to +125°C"
U12: library part CMP-0088571-2, "High-Voltage, Zero-Drift, 16-Bit ADC, I 2C, Bidirectional Shunt Current, Bus Voltage, Power, and Temperature Monitor", Manufacturer="Texas Instruments", Operating Temperature Range=to
U13: library part CMP-0097835-1, "30-mΩ, 24-V, 6-A Single-Channel Automotive Smart High-Side Switch", Manufacturer="Texas Instruments", Max Supply Voltage=48V, Min Supply Voltage=6V, Nominal Supply Current=0.98-1mA, Operating Temperature Range="-40°C to +125°C"
Y1: library part CMP-0004682-5, "Crystal, 25 MHz, 12pF, AEC-Q200 Grade 1, SMD", Frequency Stability="50 ppm", Frequency_Fixed=25MHz, Load Capacitance="12 pF", Manufacturer="Abracon Corporation"
Y2: library part CMP-0001498-1, "Low Jitter, Low Power, LVCMOS Output, BAW Oscillator", Frequency Stability=20ppm, Frequency_Fixed=25MHz, Manufacturer="Texas Instruments", Max Supply Current=5mA, Max Supply Voltage=3.63V, Min Supply Voltage=1.62V, Operating Temperature Range="-40°C to +125°C"

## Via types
v1: diameter 19.68, hole 7.87, Top Layer to Bottom Layer, tented both sides, 333 vias
v2: diameter 19.68, hole 7.87, Top Layer to Bottom Layer, 10 vias
v3: diameter 20, hole 10, Top Layer to Bottom Layer, 7 vias
v4: diameter 50, hole 28, Top Layer to Bottom Layer, 2 vias

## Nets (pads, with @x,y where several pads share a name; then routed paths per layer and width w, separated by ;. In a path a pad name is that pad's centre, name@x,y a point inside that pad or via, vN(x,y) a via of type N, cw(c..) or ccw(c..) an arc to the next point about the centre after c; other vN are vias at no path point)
!ALERT: TP11.1 U12.3 | length 186.2
  Top Layer w10: TP11.1@1134.17,-2149.78 1136.93,-2152.54 1136.93,-2180.95 v1(1138.78,-2182.8)
  Bottom Layer w6: v1@1139.2,-2183.22 1139.2,-2204.82 1150.16,-2215.78 1221.3,-2215.78 1231.18,-2205.91 1231.18,-2178.14 U12.3@1232.08,-2177.24
+1V0: L1.2 R68.1 R72.1 R74.1 TP3.1 | length 2615.1
  Signal Layer 1 w10: v1(1968.36,-3241.85) 2074.94,-3135.26 2074.94,-2065.74 2035.33,-2026.12 TP3.1@2024.09,-2026.12
  Bottom Layer w10: v1(688.63,-1501.78) 688.63,-1453.16 R72.1@690.31,-1451.47 ; R74.1@1256.1,-1501.55 1256.1,-1502.53 1269.8,-1516.23 1292.04,-1516.23 1314.43,-1538.62 v1(1316.3,-1538.62) ; R68.1@1870.21,-3550.3 1870.21,-3522.67 1893.16,-3499.72 1893.16,-3490.17 1916.11,-3467.22 1959.43,-3467.22 1969.23,-3457.42 1969.23,-3323.5 1968.36,-3322.63 v1(1968.36,-3241.85)
  Bottom Layer w20: v1(1840.66,-1291.58) 1841.53,-1290.71 1863.73,-1290.71 1998.92,-1425.91 1998.92,-2000.95 TP3.1@2024.09,-2026.12
  other v1: 1863.73,-1291.26 1852.57,-1269.28
+1V0_conn: L1.1 R16.2 R75.2 | length 144.7
  Top Layer w30: R16.2@1767.94,-1395.71 1829.89,-1395.71 L1.1@1837.32,-1403.14 1846.11,-1394.35 R75.2@1905.96,-1394.35
+1V0_FB: R36.1 R37.2 R38.2 U3.3 | length 672.3
  Top Layer w6: R38.2@1917.2,-886.9 1862.19,-941.91 1862.19,-971.99 1862.19,-1194.85 v1(1899.58,-1232.24) 1923.16,-1232.24 R37.2@1926.85,-1228.55 1926.85,-1275.32 R36.1@1930.52,-1278.99
  Top Layer w10: U3.3@1982.24,-1100.06 1982.24,-1105.77 1990.18,-1113.71 1990.18,-1124.98 v1(1992.03,-1126.83)
  Bottom Layer w10: v1(1899.58,-1232.24) 1956.64,-1232.24 1992.03,-1196.85 v1(1992.03,-1126.83)
+1V0_reg: C47.1 R34.1 R36.2 R75.1 U3.1
+3.3V_conn: J2.6 J2.8 J3.55 J3.56 R22.2
  other v1: 1638.28,-397.14 1635.06,-364.38 1637.4,-263.16
+3V3: C4.1 C5.2 C6.1 C11.1 C22.1 C31.2 C32.2 C51.1 C54.2 C55.2 C63.1 C65.1 J12.1 J16.2 J22.1 L3.1 L4.1 R3.1 R4.1 R5.1 R6.1 R14.1 R19.2 R20.2 R21.2 R22.1 R23.2 R25.2 R26.2 R27.2 R28.2 R29.1 R31.2 R32.1 R42.2 R62.1 R63.2 R64.2 R65.2 R70.2 R84.2 R85.2 R86.2 R90.1 R91.2 R93.1 R97.2 R98.2 R100.1 R104.1 R105.1 R113.1 R114.1 U3.5 U3.8 U4.8 U7.5 U8.14 U9.1 U9.16 U11.4 U12.6 | length 3466.6
  Top Layer w7: R84.2@663.88,-2495.14 664.45,-2494.56 R85.2@664.45,-2410.27
  Top Layer w10: C54.2@69.97,-2307.77 69.97,-2308.75 91.09,-2329.87 91.09,-2338.47 91.63,-2339.01 91.93,-2338.71 97.42,-2338.71 97.72,-2339.01 v1@99.44,-2339.01 ; R86.2@86.93,-2427.1 90.87,-2427.1 97.68,-2420.29 97.68,-2395.57 103.65,-2389.6 103.65,-2350.07 101.3,-2347.72 101.3,-2342.59 99.44,-2340.74 v1@99.44,-2339.01 ; U7.5@137.62,-2334.28 132.89,-2339.01 v1@99.44,-2339.01 ; v1(532.06,-2294.87) 533.91,-2296.72 544.14,-2296.72 548.3,-2300.88 ; C51.1@557.71,-2286.97 557.71,-2291.47 548.3,-2300.88 ; R85.2@664.45,-2410.27 660.52,-2410.27 578.1,-2327.85 549.77,-2327.85 U8.14@548.3,-2326.38 548.3,-2300.88 ; R5.1@1345.25,-709.76 1406.71,-709.76 R4.1@1406.98,-709.49 1407.25,-709.22 1438.09,-709.22 ; v1(1438.4,-739.2) 1438.4,-709.53 1438.09,-709.22 ; R31.2@1465.29,-1145.38 1529.62,-1145.38 1535.56,-1151.31 v1(1538.18,-1151.31) ; R29.1@1465.64,-1254.42 1530.97,-1254.42 1534.38,-1257.83 v1(1537,-1257.83) ; R3.1@1468.93,-709.22 1438.09,-709.22 ; v1(2002.09,-962.61) 2002.09,-965.23 2006.73,-969.87 2006.73,-988.72 U3.5@2007.83,-989.83
  Top Layer w15.75: U3.8@1931.06,-989.83 1931.06,-974.75
  Signal Layer 2 w10: J12.1@758.98,-1494.51 831.12,-1566.65 v1(831.12,-1762.48)
  Bottom Layer w10: v1(92.95,-2336.86) 108.52,-2336.86 112.38,-2340.72 U9.16@112.38,-2342.19 ; R21.2@113.52,-537.42 113.52,-502.57 124.11,-491.99 v3(124.11,-489.29) ; R32.1@307.7,-1006.28 307.84,-1006.14 v1(307.84,-965.54) ; v1(363.62,-437.63) 399.14,-437.63 R65.2@399.38,-437.39 399.71,-437.05 C5.2@448.63,-437.05 470.89,-437.05 476.82,-442.99 476.82,-542.47 466.88,-552.42 U4.8@450.14,-552.42 ; R26.2@405.32,-1536.11 v1(405.32,-1576.05) 405.32,-1615.99 R28.2@406.2,-1616.86 ; R27.2@408.93,-1956.24 409.2,-1955.97 v1(409.2,-1915.18) R25.2@409.2,-1874.4 ; R23.2@496.82,-859.54 R23.2@496.92,-859.44 496.92,-855.5 503.73,-848.69 520.21,-848.69 v1(520.95,-847.95) 521.69,-848.69 537.39,-848.69 544.21,-855.5 R63.2@544.21,-859.44 ; v1(573.19,-1269.05) 595.37,-1291.24 R100.1@625.21,-1291.24 ; R62.1@1099.75,-1599.92 1099.75,-1537.32 1099.24,-1536.8 1139.75,-1536.8 1149.13,-1546.18 v1(1151.75,-1546.18) ; R105.1@1178.88,-2090.82 1198.71,-2090.82 ; v1(1198.71,-2068.42) 1198.71,-2090.82 ; R104.1@1218.53,-2090.82 1198.71,-2090.82 ; U12.6@1271.45,-2350.47 1271.45,-2343.31 1272.36,-2342.41 1291.91,-2342.41 ; v1(1293.22,-2323.78) 1291.91,-2325.09 1291.91,-2342.41 ; C65.1@1311.46,-2342.41 1291.91,-2342.41 ; R14.1@1503.74,-1245.11 1516.46,-1257.83 v1(1537,-1257.83) 1537,-1260.45 1542.31,-1265.76 1542.31,-1387.52 1507.64,-1387.52 R6.1@1505.26,-1385.13 ; R114.1@1533.12,-2541.58 1533.37,-2541.82 1533.37,-2580.26 R113.1@1533.62,-2580.51 1535.18,-2582.07 1535.18,-2675.2 v1(1536.75,-2676.77) 1536.75,-2715.43 1542.6,-2721.28 1579.83,-2758.51 1594,-2758.51 J22.1@1614.54,-2779.06 ; R20.2@1552.78,-851.68 1560.65,-851.68 1592.18,-883.2 v1(1592.18,-884.47) ; R19.2@1599.34,-631.06 1599.34,-589.17 1613.07,-575.45 v1(1613.07,-572.82) ; v1(1681.9,-3557.67) 1704.36,-3557.67 1709.2,-3552.83 R93.1@1709.2,-3551.6 ; R98.2@1744.29,-861.27 R98.2@1744.81,-861.79 ; R42.2@1772.43,-2775.51 1780.31,-2775.51 1787.88,-2783.08 R70.2@1823.87,-2783.08 1825.25,-2781.7 1845.87,-2781.7 ; v1(1852.45,-2754.22) 1850.6,-2756.07 1850.6,-2776.97 1845.87,-2781.7 ; U11.4@1912.34,-2780.06 1910.7,-2781.7 C63.1@1866.49,-2781.7 1845.87,-2781.7 ; C6.1@2070.28,-985.83 C6.1@2070.81,-986.35
  Bottom Layer w20: C32.2@1945.23,-974.28 1990.41,-974.28 v1(2002.09,-962.61) ; C31.2@1982.84,-902.92 1997.6,-917.69 1997.6,-947.08 2001.53,-951.01 ; v1@2002.35,-962.34 2025.83,-985.83 C6.1@2070.28,-985.83
  Bottom Layer w30: C11.1@671.45,-1032.46 730.72,-1032.46 L3.1@731.41,-1031.77 745.11,-1018.07 745.11,-994.84 747.53,-992.42 v1(747.53,-829.56) 747.01,-829.05 747.01,-797.69 R64.2@746.5,-797.17 ; v1(831.12,-1762.48) 833.67,-1765.02 906.37,-1765.02 ; L4.1@907.09,-1710.47 907.22,-1710.6 907.22,-1764.89
  other v1: 89.9,-2085.91 1798.58,-1150.78 1690.15,-1146.29 1799.39,-1116.54 1690.96,-1116.13 1692.59,-1084.74 1796.95,-1078.63 1939.37,-963.82 1829.07,-933.12 1802.97,-917.61 1638.86,-912.87 1576.67,-910.57 1607.24,-911.08 1829.58,-902.55 1803.48,-887.04 1622.75,-884.98 1831.37,-870.93
+6V: C48.2 R66.2 R76.2 R77.2 R78.2 U5.1 U6.5 | length 1568.9
  Top Layer w10: R76.2@287.08,-2699.12 300.78,-2712.82 317.09,-2712.82 327.86,-2723.58 v1(330.48,-2723.58) ; U6.5@315.67,-3010.95 318.9,-3007.73 318.9,-2963.53 327.31,-2955.11 v1(327.31,-2952.57) ; R77.2@502.17,-2837.74 502.17,-2837.54 515.87,-2823.84 515.87,-2823.06 544.42,-2823.06 v1(545.88,-2821.6)
  Signal Layer 1 w30: v1(545.88,-2821.6) 701.21,-2821.6 855.52,-2975.91 1405.43,-2975.91 v1(1647.38,-3217.87)
  Bottom Layer w10: v1(330.48,-2723.58) 330.48,-2789.44 336.34,-2795.29 R78.2@359.06,-2795.29 ; v1(1647.38,-3217.87) 1647.38,-3254.89 R66.2@1648.55,-3256.05
+12V: C49.1 J20.3 J21.3 R1.2 R15.1 R33.2 R61.2 U5.5 U5.8 | length 361.1
  Bottom Layer w10: R61.2@1567.65,-3386.47 1567.83,-3386.29 v1(1567.83,-3338.4)
  Bottom Layer w20: U5.5@514.2,-2718.36 526.6,-2718.36 541.02,-2732.78 541.02,-2780.71 531.09,-2790.64 526.83,-2790.64 526.24,-2791.24 516.02,-2791.24 514.2,-2793.05 514.2,-2822.99 523.4,-2832.18 C49.1@523.4,-2847.86 525.4,-2849.86 535.36,-2849.86 549.58,-2864.08 v1(549.58,-2865.4)
  Bottom Layer w30: R33.2@1752.9,-3256.05 v1(1803.69,-3256.05) 1859.52,-3256.05 R1.2@1860.09,-3256.63
  other v4: 2012.77,-440.73
+12V_conn: J2.2 J3.27 J3.28 R15.2
  other v1: 1418.94,-374.76 1426.1,-334.34 1392.32,-333.36
  other v4: 1822.97,-159.14
A0: J3.14 R23.1 U4.1 | length 775.3
  Bottom Layer w10: R23.1@497.43,-811.68 497.43,-807.74 503.73,-801.44 507.66,-801.44 551.98,-757.12 551.98,-590.57 590.13,-552.42 U4.1@664.71,-552.42 843.78,-552.42 926.29,-469.91 989.36,-469.91 1000.63,-458.64 1000.63,-438.11 J3.14@1004.49,-434.25
A1: J3.15 R63.1 U4.2 | length 883.2
  Signal Layer 2 w10: v1(956.36,-489.91) 957.24,-489.91 990.03,-522.7 990.03,-523.58 1008.85,-542.4 1050.74,-542.4 1065.01,-528.12 v1(1067.72,-528.12)
  Bottom Layer w10: R63.1@544.21,-812.19 544.21,-808.26 571.64,-780.82 571.64,-629.43 598.65,-602.42 U4.2@664.71,-602.42 829.28,-602.42 941.4,-490.3 955.96,-490.3 v1(956.36,-489.91) ; J3.15@1035.98,-434.25 1035.98,-469.89 1067.72,-501.63 v1(1067.72,-528.12)
A2: J3.16 R64.1 U4.3 | length 742
  Signal Layer 2 w10: v1(956.96,-517.92) 1000.91,-561.87 v1(1080.63,-561.87)
  Bottom Layer w10: U4.3@664.71,-652.42 717.82,-652.42 ; R64.1@746.5,-749.93 746.5,-681.09 717.82,-652.42 ; v1(956.96,-517.92) 822.46,-652.42 717.82,-652.42 ; J3.16@1067.48,-434.25 1067.48,-472.72 1092.4,-497.65 1092.4,-550.09 v1(1080.63,-561.87)
AE_ATP0: TP2.1 U1.20 | length 305.5
  Top Layer w10: U1.20@1159.75,-1311.91 1209.77,-1311.91 1209.91,-1312.06 1214.47,-1307.49 1286.75,-1307.49 1289.59,-1310.34 v1(1292.21,-1310.34) ; v1(1349.68,-1350.3) 1384.51,-1385.13 TP2.1@1431.11,-1385.13
  Bottom Layer w10: v1(1292.21,-1310.34) 1294.07,-1312.19 1311.57,-1312.19 v1(1349.68,-1350.3)
AE_CLKOUT: C42.1 TP6.1 U1.16 | length 384.8
  Top Layer w9: U1.16@1084.95,-1367.03 1084.95,-1407.18 1086.93,-1409.17 1127.56,-1449.79 1147.89,-1449.79 v1(1149.16,-1451.06)
  Top Layer w10: v1(1204.08,-1497.2) 1281.56,-1497.2 C42.1@1284.55,-1500.19 1284.44,-1500.3 TP6.1@1284.44,-1606.65
  Bottom Layer w10: v1(1149.16,-1451.06) 1151.01,-1452.92 1159.8,-1452.92 v1(1204.08,-1497.2)
AE_INH: J2.97 J3.47 J19.1 R60.1 U1.10 | length 4192.7
  Top Layer w6: v1(260.39,-162.69) 95.92,-162.69 59.78,-198.83 59.78,-1123.59 105.59,-1169.4 105.59,-1172.14 113.14,-1179.69 113.14,-1631.65 141.2,-1659.71 v1(439.05,-1659.71) 503.58,-1659.71 796.2,-1367.09 870.4,-1367.09 931.67,-1428.36 949.52,-1428.36 966.84,-1411.04 U1.10@966.84,-1367.03
  Signal Layer 2 w10: v1(260.39,-162.69) 260.39,-99.5 298.17,-61.73 688.26,-61.73 910.69,-284.15 910.69,-336.32 916.55,-342.18 941.52,-342.18 954.05,-329.65 954.05,-328.23 966.62,-315.66 v1(966.62,-314.38)
  Bottom Layer w9: v1(260.39,-162.69) 279.31,-162.69 280.29,-161.71 296.68,-161.71 316.57,-141.82 J2.97@316.57,-77
  Bottom Layer w10: v1(105.52,-1169.33) 180.76,-1169.33 J19.1@195.56,-1154.53 184.06,-1143.04 R60.1@184.06,-1060.75 ; v1(966.62,-314.38) 966.62,-312.96 1052.25,-227.32 1079.34,-227.32 1085.42,-221.24 1086.2,-221.24 1098.98,-208.46 J3.47@1098.98,-195.67
AE_INT_N: J2.100 J3.31 J4.1 R32.2 U1.2 | length 2787.5
  Top Layer w6: v1(93.15,-1199.54) 91.72,-1199.54 46.52,-1154.34 46.52,-190.52 95.03,-142 v1@233.08,-142 ; v1(235.25,-142) 275.59,-142 285.28,-132.32 285.28,-77.2 J2.100@285.08,-77 ; v1(454.73,-1154.49) 454.31,-1154.07 454.31,-1124.87 462.65,-1116.52 804.94,-1116.52 882.37,-1193.94 U1.2@931.41,-1193.94
  Top Layer w10: v1@233.08,-142 v1(235.25,-142)
  Bottom Layer w6: v1(235.25,-142) 236.64,-143.39 236.64,-167 252.18,-182.53 279.97,-182.53 286.29,-176.21 395.18,-176.21 422.68,-203.71 591.18,-203.71 595.04,-199.85 J3.31@595.04,-195.67 ; J4.1@361.19,-1154.49 v1(454.73,-1154.49)
  Bottom Layer w7.87: v1(93.15,-1199.54) 315.62,-1199.54 J4.1@360.93,-1154.23 307.7,-1101 R32.2@307.7,-1069.27
  Bottom Layer w10: J4.1@360.93,-1154.23 J4.1@361.19,-1154.49
AE_LED_0: J5.2 U1.35 | length 1469.4
  Top Layer w6: v1(282.34,-1556.44) 281.12,-1555.22 281.12,-1490.32 233.62,-1442.82 233.62,-1366.54 271.2,-1328.97 412.86,-1328.97 436.84,-1304.99 436.84,-1114.93 454.62,-1097.15 853.12,-1097.15 911.06,-1039.21 969.14,-1039.21 986.12,-1056.19 U1.35@986.12,-1138.68
  Bottom Layer w6: J5.2@281.12,-1726.33 281.73,-1725.72 281.73,-1557.05 v1(282.34,-1556.44)
AE_LED_1: J6.2 U1.6 | length 998.1
  Top Layer w6: J6.2@281.12,-1386.33 310.5,-1415.71 310.5,-1563.96 323.41,-1576.87 377,-1576.87 408.22,-1608.09 448.77,-1608.09 456.14,-1615.46 500.39,-1615.46 774.79,-1341.06 834.3,-1341.06 846.2,-1329.16 846.2,-1288.28 861.79,-1272.69 U1.6@931.41,-1272.69
  Top Layer w10: J6.2@281.12,-1386.33 J6.2@281.12,-1386.22
AE_MDC: J9.1 U1.1 | length 1533.3
  Top Layer w6: U1.1@931.41,-1174.26 889.79,-1174.26 882.2,-1166.66 882.2,-1100.09 922.31,-1059.98 v1(959.06,-1059.98) ; v1(1344.22,-1132.34) 1346.74,-1129.82 1356.34,-1129.82 1519.21,-966.95 1648.78,-966.95 1689.02,-926.71 1689.02,-765.44 1775.58,-678.88 1901.28,-678.88 J9.1@1948.25,-631.91
  Bottom Layer w6: v1(959.06,-1059.98) 962.76,-1059.98 972.43,-1069.65 1281.52,-1069.65 v1(1344.22,-1132.34)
